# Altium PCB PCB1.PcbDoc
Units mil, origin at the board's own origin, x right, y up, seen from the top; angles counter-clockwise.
Board outline 6000 x 4000 mil, 2 copper layers (Top Layer, Bottom Layer); 3 components, 3 nets, 9 pads, 0 vias.
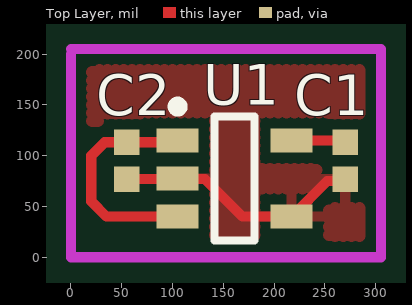
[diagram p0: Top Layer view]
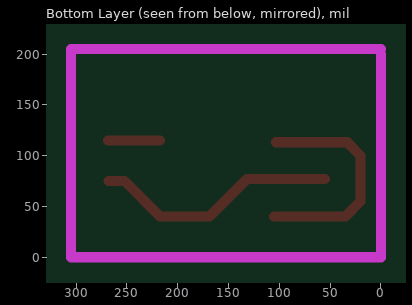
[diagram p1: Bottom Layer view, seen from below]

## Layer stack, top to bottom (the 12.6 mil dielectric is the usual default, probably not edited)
Top Solder: solder mask 0.4, Solder Resist, Dk 3.5
Top Layer: signal copper 1.4
Dielectric 1: dielectric 12.6, FR-4, Dk 4.8
Bottom Layer: signal copper 1.4
Bottom Solder: solder mask 0.4, Solder Resist, Dk 3.5

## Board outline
-540,-570 5460,-570 5460,3430 -540,3430

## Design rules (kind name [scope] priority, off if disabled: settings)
Clearance [All] p1: gap=10
PolygonConnect [All] p1: connectstyle=Relief reliefconductorwidth=10 reliefentries=4 polygonreliefangle="90 Angle" airgapwidth=10
RoutingVias [All] p1: holewidth=28 width=50 viastyle="Through Hole" minholewidth=28 minwidth=50 maxholewidth=28 maxwidth=50
SolderMaskExpansion [All] p1: expansion=4
UnpouredPolygon [All] p1: allowunpoured=FALSE
Width [All] p1: maxlimit=100 minlimit=4 preferedwidth=10
29 further rules are at their usual default settings.

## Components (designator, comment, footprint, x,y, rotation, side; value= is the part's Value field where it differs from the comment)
C1 "1uF" CAPC1005X06N 270,95 r270 top
C2 "100nF" CAPC1005X06N 55,95 r270 top
U1 "MCP1802" MCP1802_SOT23-5 161.1,77.4 r0 top

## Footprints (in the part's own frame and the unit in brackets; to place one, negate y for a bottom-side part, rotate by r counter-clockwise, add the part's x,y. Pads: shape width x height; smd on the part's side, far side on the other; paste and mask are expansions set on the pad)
CAPC1005X06N [mm] "Chip Capacitor, 2-Leads, Body 1.00x0.50mm, IPC Medium Density"
  rect 0.64x0.64 smd: 1(-0.46,0) 2(0.46,0)
  body extent -0.55,-0.3 0.55,0.3, height 0.6
MCP1802_SOT23-5 [mm] "SOT23, 5-Leads, Body 2.90x2.70mm, Pitch 0.95mm, IPC Medium Density"
  rect 1.05x0.6 smd: 1(-1.425,0.95) 2(-1.425,0) 3(-1.425,-0.95) 4(1.425,-0.95) 5(1.425,0.95)
  silkscreen extent -1.55,-1.55 0.5,1.92, body extent -0.9,-1.55 0.9,1.55, height 1.45

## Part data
C1 C2: library part Cap
U1: "300 mA, High PSRR, Low Quiescent Current LDO"

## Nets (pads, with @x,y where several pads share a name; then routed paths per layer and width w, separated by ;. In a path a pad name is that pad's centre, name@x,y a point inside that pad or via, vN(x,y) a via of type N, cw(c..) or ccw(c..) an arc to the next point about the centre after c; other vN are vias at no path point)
+5VIN: C2.1 U1.1 U1.3 | length 224.9
  Top Layer w10: U1.1@103.31,113.11 C2.1 33.11,113.11 20,100 20,55 35,40 U1.3
+VCC: C1.1 U1.5 | length 51.1
  Top Layer w10: U1.5 C1.1@268.31,114.8
GND: C1.2 C2.2 U1.2 U1.4 | length 242.9
  Top Layer w10: C2.2 131.89,76.89 168.78,40 U1.4 252.2,75 C1.2@268.11,75

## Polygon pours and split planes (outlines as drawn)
GND on Top Layer "GND" (hatched 90Degree grid 8 track 12, remove dead copper, pour order 3): 5,205 305,205 305,0 0,0 0,205 5,205

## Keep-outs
Keep-Out Layer:
  lines w10: 0,200 0,0 305,0 305,205 5,205 0,205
